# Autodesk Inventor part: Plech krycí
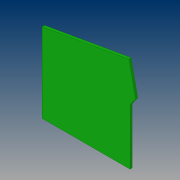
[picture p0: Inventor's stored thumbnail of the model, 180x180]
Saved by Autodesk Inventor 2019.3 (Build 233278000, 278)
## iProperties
Created: 2019-03
Part Number: Plech krycí
Material: Ocel, legovaná
Document SubType Name: Plech
Designer: B-hon
Density: 7.73 g/cm^3
Sheet Metal Rule: Výchozí_mm
Appearance: Tmavě zelená
Mass: 93.1445 g
Surface Area: 126.675 cm^2
Volume: 12.0497 cm^3
Author: B-hon
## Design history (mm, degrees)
node "Plocha1"
  sketch "Náčrt1"
    geometry: L1 (102.033, 0)-(102.033, 28); L2 (39.033, 70.62)-(-31.587, 0); L3 (102.033, 0)-(-31.587, 0); L4 (102.033, 28)-(144.953, 89.297); L5 (102.033, 28)-(153.095, 28); L6 (39.033, 70.62)-(144.953, 89.297); 1 further point
    constraints: 12 end point, 2 horizontal, 1 perpendicular, 1 point on line
    dimensions: "d1" = 63 distance from line of L2.start L1; "d4" = 55 deg angle of L5 L4; "d5" = 28 distance of L1.start L1.end; "d6" = 45 deg angle of L3 L2; "d23" = 10 deg angle of L6 L3
sketch "Náčrt4"
  geometry: L1 (132.151, -6.311)-(108.806, 103.521); L2 (108.806, 103.521)-(191.325, 96.019); L3 (191.325, 96.019)-(132.151, -6.311); L4 (-27.587, 4)-(102.033, 4) reference; 2 further points
  constraints: 6 end point
  dimensions: "d24" = 78 deg angle of L4 L1; "d25" = 32.4 distance from line of point (144.953, 89.297) L1
extrude "Vysunutí2" cut sketch "Náčrt4" distance "d26" = 10; taper "d27" = 0 deg
sketch "Náčrt5"
  geometry: L1 (-48.033, 122.158)-(109.903, 122.158); L2 (109.903, 122.158)-(109.903, -64.439); L3 (109.903, -64.439)-(-48.033, -64.439); L4 (-48.033, -64.439)-(-48.033, 122.158); L5 (31.587, 2)-(31.587, 0) reference; 1 further point
  constraints: 8 end point, 2 parallel, 1 horizontal, 1 perpendicular
  dimensions: "d28" = 79.62 distance between parallel lines of L5 L4
extrude "Vysunutí3" cut sketch "Náčrt5" extent not by distance; stored distance "d29" = 0; taper "d30" = 0 deg
node "Upravit přímo1"
node "Upravit přímo2"
node "Upravit přímo3"
node "Těleso1"
feature "Deska1" dims "d7" = 2 (= Tloušťka)
feature "Posunout1" dims "d33" = 15
feature "Posunout2" dims "d36" = 9
feature "Posunout3" dims "d39" = 3
other parameters: "Tloušťka" = 2, "KSoučinitel" = 4.4, "PoloměrOhybu" = 2 (= Tloušťka), "ŠířkaVýštipu" = 2 (= Tloušťka), "HloubkaVýštipu" = 1 (= 0.5 x Tloušťka), "VelikostRohovéhoVýštipu" = 8 (= 4 x Tloušťka), "MezeraVystřižení" = 0.01, "MinimálníZbytek" = 4 (= 2 x Tloušťka), "PřechodovýPoloměr" = 2 (= PoloměrOhybu), "VelikostJacobihoPoloměru" = 2 (= PoloměrOhybu), "VelikostMezery" = 2 (= Tloušťka), "d31" = 0, "d32" = 0, "d34" = 0, "d35" = 0, "d37" = 0, "d38" = 0
